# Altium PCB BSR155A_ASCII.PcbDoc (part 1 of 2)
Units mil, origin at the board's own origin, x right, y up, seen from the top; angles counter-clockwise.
Board outline 3250 x 2500 mil, 4 copper layers (Top Layer, MidLayer1, MidLayer2, Bottom Layer), stack 59.8 mil thick; 70 components, 25 nets, 149 pads, 70 vias.
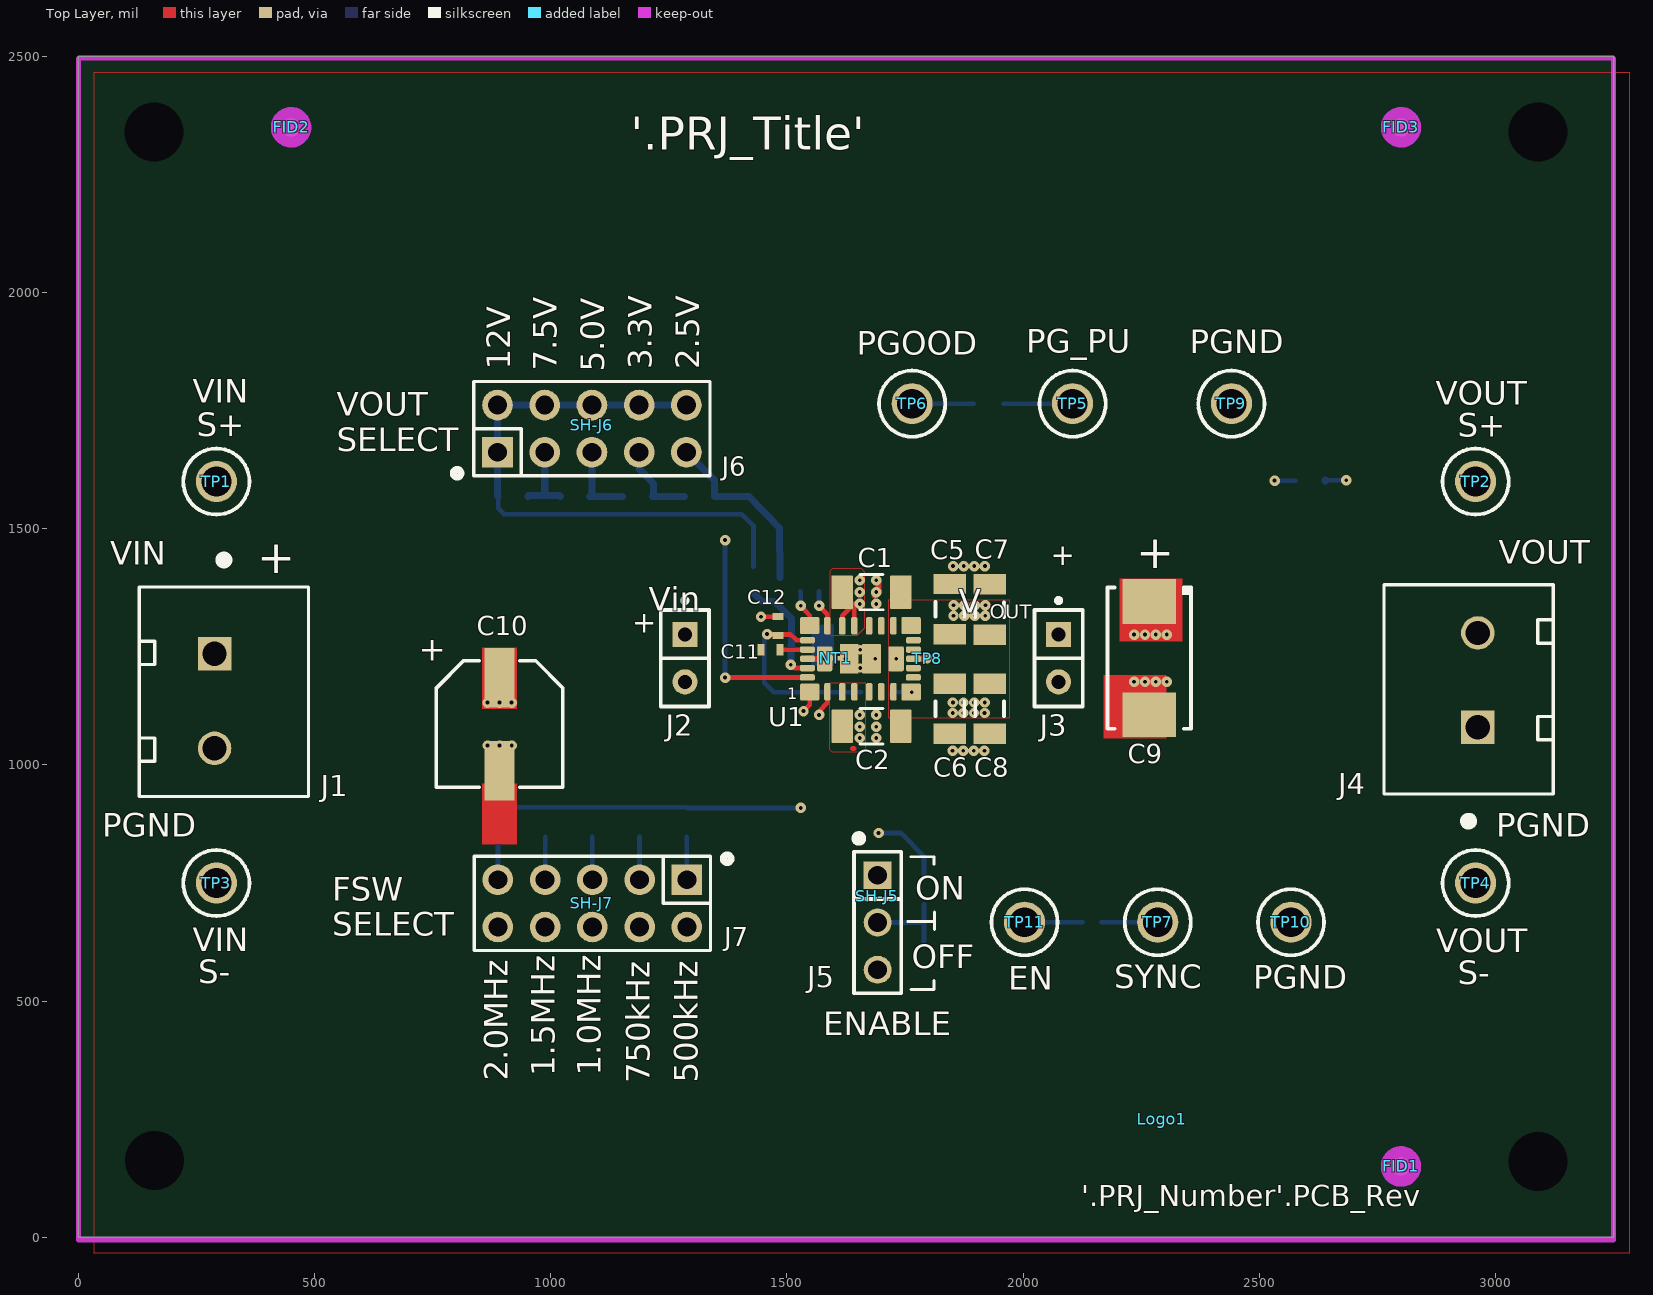
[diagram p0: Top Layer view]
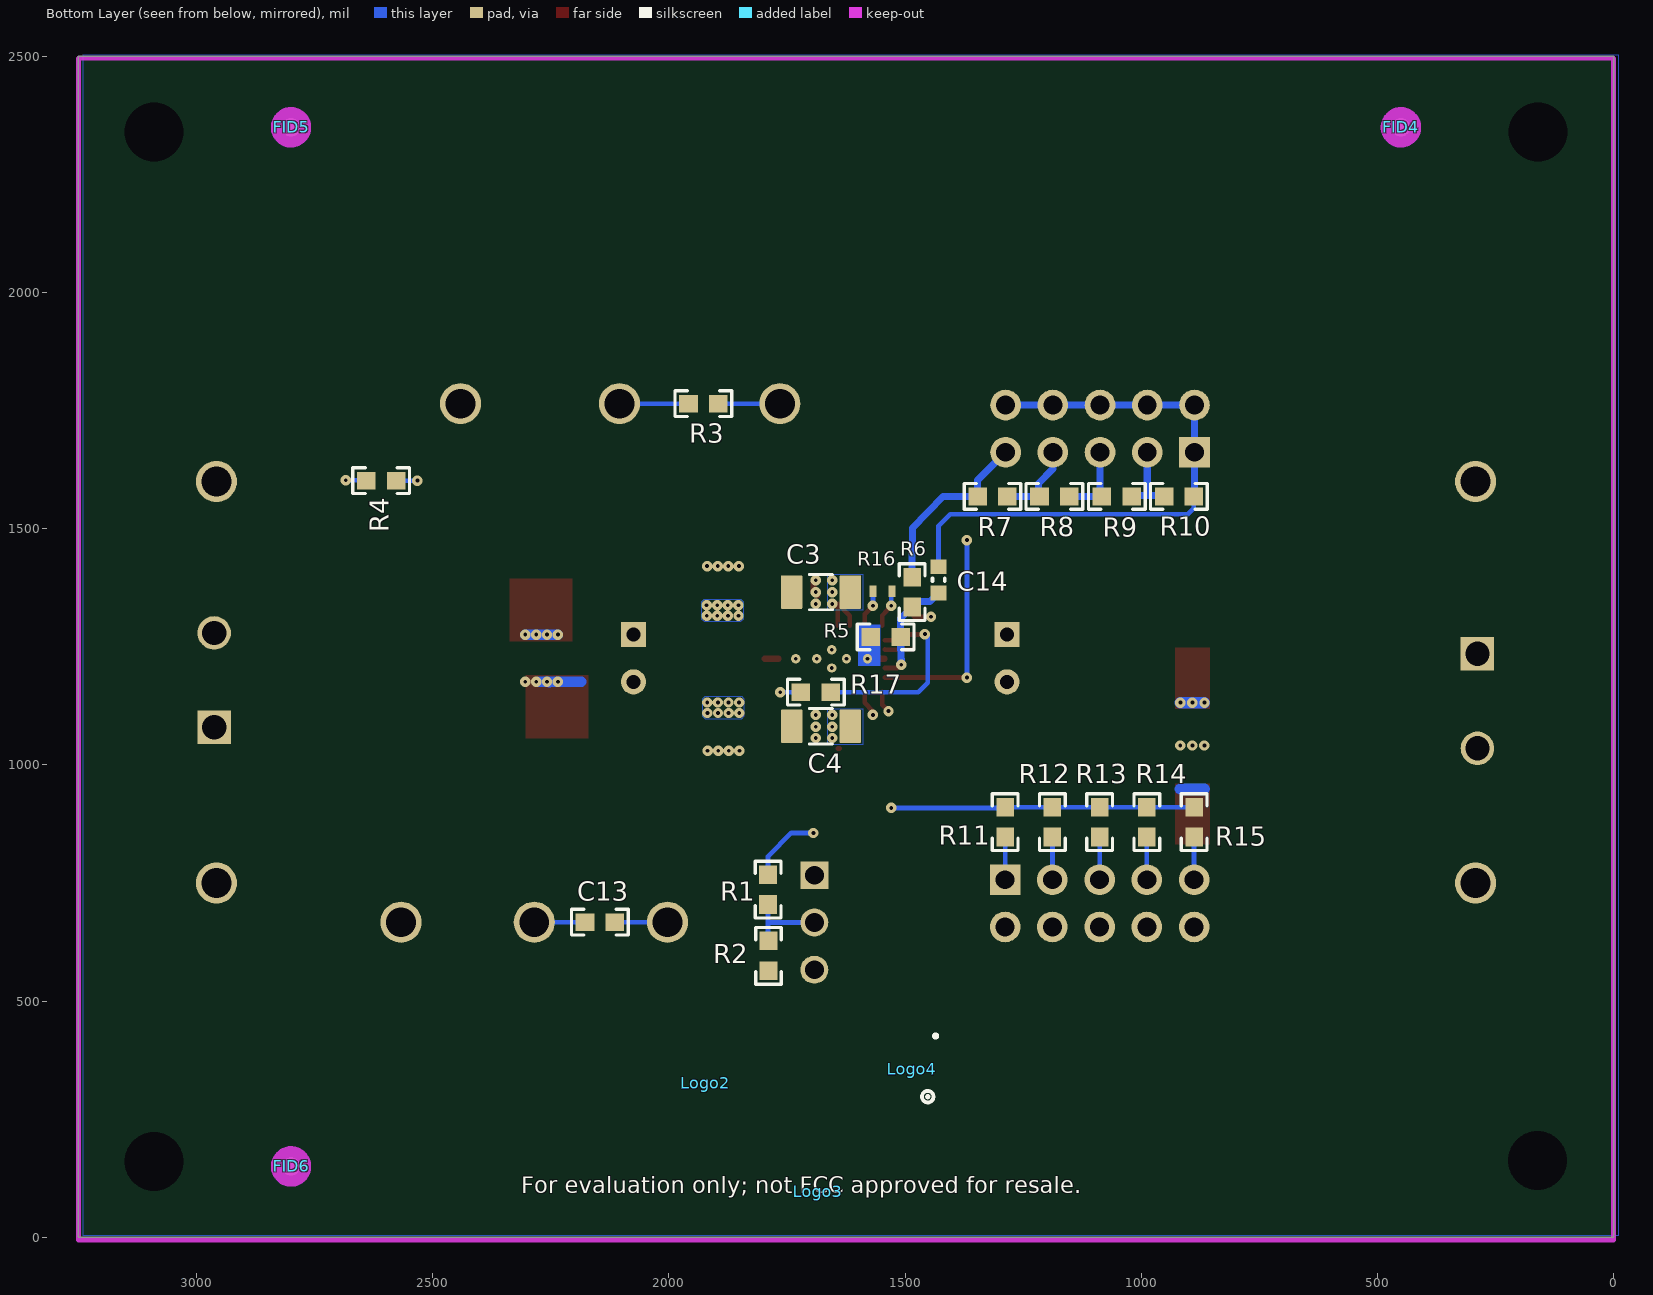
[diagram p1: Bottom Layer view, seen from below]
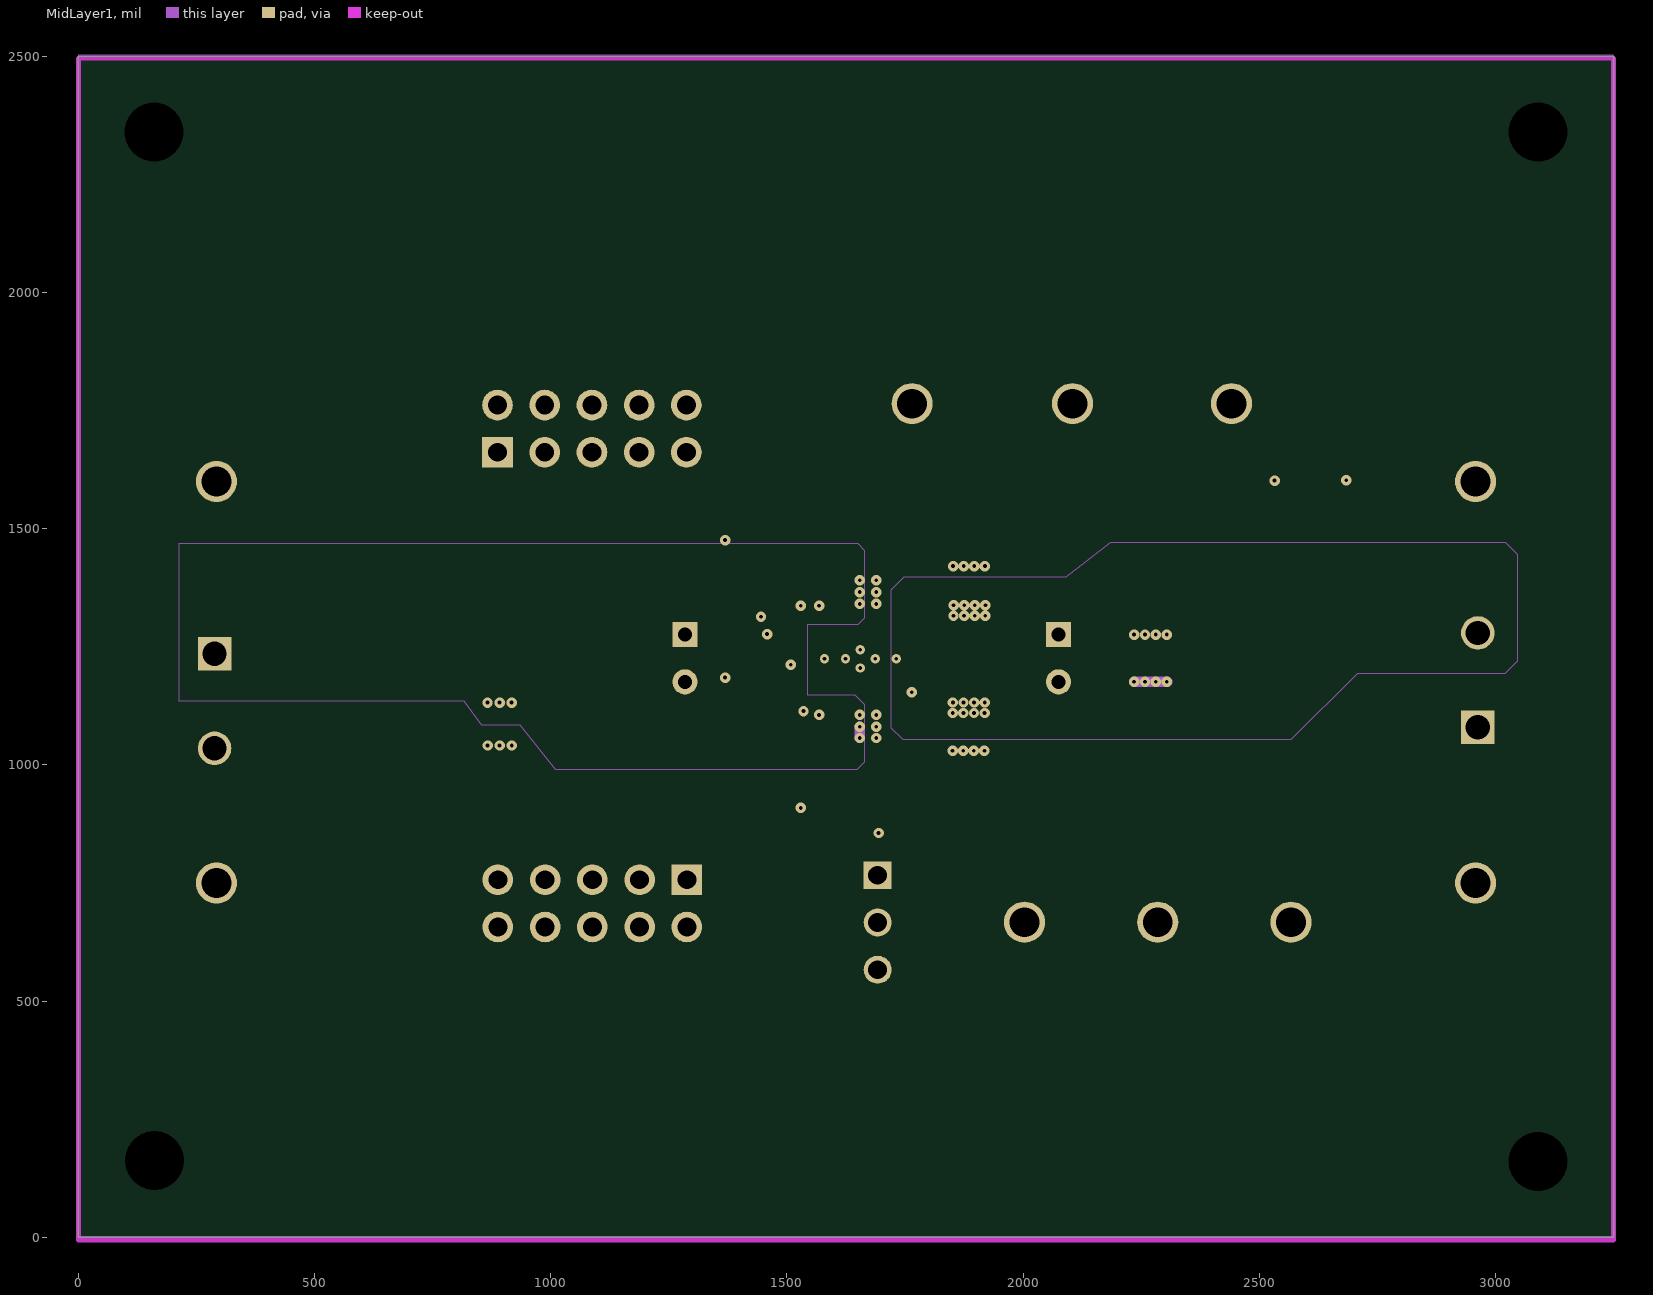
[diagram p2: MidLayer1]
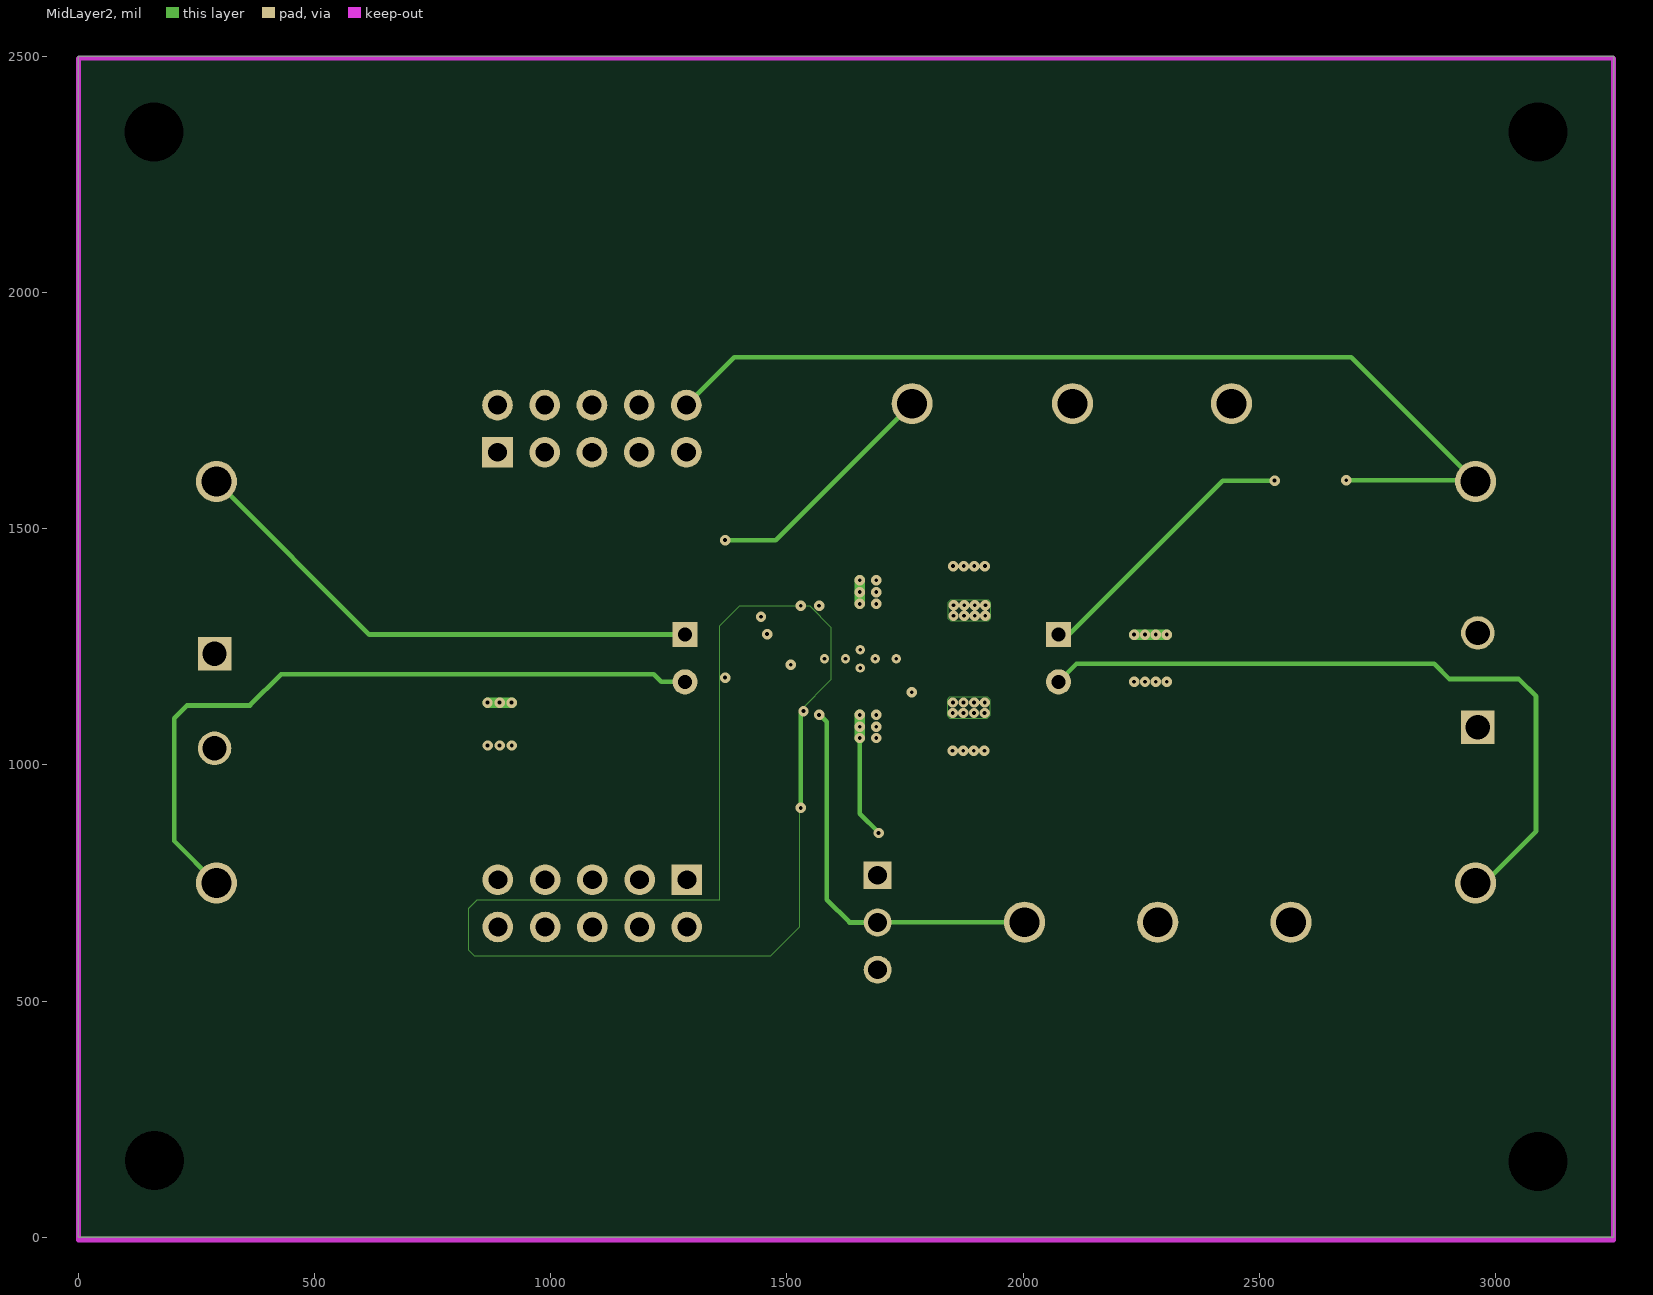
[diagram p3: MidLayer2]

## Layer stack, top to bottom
Top Solder: solder mask 0.4, Solder Resist, Dk 3.5
Top Layer: signal copper 1.4
Dielectric1: prepreg 5, FR-4 High Tg, Dk 4.2
MidLayer1: signal copper 2.8
Dielectric2: core 40, FR-4 High Tg, Dk 4.2
MidLayer2: signal copper 2.8
Dielectric3: prepreg 5, FR-4 High Tg, Dk 4.2
Bottom Layer: signal copper 2.8
Bottom Solder: solder mask 0.4, Solder Resist, Dk 3.5

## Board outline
0,0 0,2500 3250,2500 3250,0

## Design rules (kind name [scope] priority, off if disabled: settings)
AcuteAngle [All] p0: scope1count=1 scope1_0_kind=Board scope1_0_value=Board scope2count=1 scope2_0_kind=Board scope2_0_value=Board commentlength=0 minimum=4.50000000000000E+0001
AcuteAngle [All] p1: minimum=4.50000000000000E+0001 checktracksonly=TRUE
AssemblyTestPointUsage [All] p0: scope1count=1 scope1_0_kind=Board scope1_0_value=Board scope2count=1 scope2_0_kind=Board scope2_0_value=Board commentlength=0
AssemblyTestPointUsage [All] p1: valid=2
AssemblyTestpoint [All] p0: scope1count=1 scope1_0_kind=Board scope1_0_value=Board scope2count=1 scope2_0_kind=Board scope2_0_value=Board commentlength=0
BoardOutlineClearance [All] p0 off: scope1count=1 scope1_0_kind=Board scope1_0_value=Board scope2count=1 scope2_0_kind=Board scope2_0_value=Board commentlength=172 gap=20 // Protel DXP Scope 1 Expression Was: OnCopper and Not InComponentClass('Logo') and not InComponentClass('FiducialMark') and not InRegion(1000,500,4000,800) and not InPoly
BoardOutlineClearance BoardOutlineClearance_Poly [All] p0 off: scope1count=1 scope1_0_kind=Board scope1_0_value=Board scope2count=1 scope2_0_kind=Board scope2_0_value=Board commentlength=58 gap=20 // Protel DXP Scope 1 Expression Was: OnCopper and IsPoly
BoardOutlineClearance BoardOutlineClearance_MountingHoles [All] p0 off: scope1count=1 scope1_0_kind=Board scope1_0_value=Board scope2count=1 scope2_0_kind=Board scope2_0_value=Board commentlength=86 gap=40 // Protel DXP Scope 1 Expression Was: OnCopper and InComponentClass('Mounting Holes')
BoardOutlineClearance BoardOutlineClearance_MountingHoles [OnCopper and InComponentClass('Mounting Holes')] p1: gap=40 ignorepadtopadclearanceinfootprint=FALSE
BoardOutlineClearance BoardOutlineClearance_Poly [OnCopper and IsPoly] p2: gap=20 ignorepadtopadclearanceinfootprint=FALSE
BoardOutlineClearance [OnCopper and Not InComponentClass('Logo') and not InComponentClass('FiducialMark') and not InRegion(1000,500,4000,800) and not InPoly] p3: gap=20 ignorepadtopadclearanceinfootprint=FALSE
Clearance [All] p0: scope1count=1 scope1_0_kind=Board scope1_0_value=Board scope2count=1 scope2_0_kind=Board scope2_0_value=Board commentlength=0 gap=10
Clearance Clearance_FiducialMark [All] p0 off: scope1count=1 scope1_0_kind=Board scope1_0_value=Board scope2count=1 scope2_0_kind=Board scope2_0_value=Board commentlength=81 gap=0 // Protel DXP Scope 2 Expression Was: IsPad and InComponentClass('FiducialMark')
Clearance Clearance_Poly [All] p0 off: scope1count=1 scope1_0_kind=Board scope1_0_value=Board scope2count=1 scope2_0_kind=Board scope2_0_value=Board commentlength=48 gap=10 // Protel DXP Scope 1 Expression Was: InPolygon
Clearance Clearance_Keepouts [All] p0 off: scope1count=1 scope1_0_kind=Board scope1_0_value=Board scope2count=1 scope2_0_kind=Board scope2_0_value=Board commentlength=99 gap=0 // Protel DXP Scope 2 Expression Was: ((IsTrack Or IsArc) And Not InPoly) And IsFree and IsKeepOut
Clearance Clearance_Keepouts [((IsTrack Or IsArc) And Not InPoly) And IsFree and IsKeepOut vs ((IsTrack Or IsArc) And Not InPoly) And IsFree and IsKeepOut] p1: gap=0 ignorepadtopadclearanceinfootprint=FALSE
Clearance Clearance_Poly [InPolygon] p2: gap=10 ignorepadtopadclearanceinfootprint=FALSE except(0: Arc-Hole Track-Hole SMDPad-Hole THPad-Hole Via-Hole Fill-Hole Poly-Hole Region-Hole Text-Hole)
Clearance Clearance_FiducialMark [IsKeepOut and InComponentClass('FiducialMark') vs IsPad and InComponentClass('FiducialMark')] p3: gap=0 ignorepadtopadclearanceinfootprint=FALSE
Clearance [All] p4: gap=10 ignorepadtopadclearanceinfootprint=FALSE except(0: Arc-Hole Track-Hole SMDPad-Hole THPad-Hole Via-Hole Fill-Hole Poly-Hole Region-Hole Text-Hole; 4: SMDPad-SMDPad; 6: Arc-SMDPad Track-SMDPad SMDPad-THPad; 8: Arc-Arc Arc-Track Track-Track)
ComponentClearance "ComponentClearance_U1 to NT1" [All] p0: scope1count=1 scope1_0_kind=Component scope1_0_value=NT1 scope2count=1 scope2_0_kind=Component scope2_0_value=U1 commentlength=0 gap=0 collisioncheckmode=3
ComponentClearance [All] p0: scope1count=1 scope1_0_kind=Board scope1_0_value=Board scope2count=1 scope2_0_kind=Board scope2_0_value=Board commentlength=0 gap=10 collisioncheckmode=3
ComponentClearance ComponentClearance_THtoTH [All] p0 off: scope1count=1 scope1_0_kind=Board scope1_0_value=Board scope2count=1 scope2_0_kind=Board scope2_0_value=Board commentlength=54 gap=10 collisioncheckmode=3 // Protel DXP Scope 2 Expression Was: IsThruComponent
ComponentClearance ComponentClearance_THtoSMT [All] p0 off: scope1count=1 scope1_0_kind=Board scope1_0_value=Board scope2count=1 scope2_0_kind=Board scope2_0_value=Board commentlength=53 gap=10 collisioncheckmode=3 // Protel DXP Scope 2 Expression Was: IsSMTComponent
ComponentClearance ComponentClearance_SmallPassives [All] p0 off: scope1count=1 scope1_0_kind=Board scope1_0_value=Board scope2count=1 scope2_0_kind=Board scope2_0_value=Board commentlength=508 gap=8 collisioncheckmode=3 // Protel DXP Scope 2 Expression Was: HasFootprint('0201*') or HasFootprint('0402*') or HasFootprint('0508') or HasFootprint('0603*') or HasFootprint('0612') or HasFootprint('0805*') or HasFootprint('0815*') or HasFootprint('0830*') or HasFootprint('1206*') or HasFootprint('1210*') or HasFootprint('1808*') or HasFootprint('1812*') or HasFootprint('1825*') or HasFootprint('2010*') or HasFootprint('2220*') or HasFootprint('2225*') or HasFootprint('2512*') or HasFootprint('2728*') or HasFootprint('3518*')
ComponentClearance ComponentClearance_MountingHoles [All] p0: scope1count=1 scope1_0_kind=ComponentClass scope1_0_value="Mounting Holes" scope2count=1 scope2_0_kind=Board scope2_0_value=Board commentlength=0 gap=10 collisioncheckmode=3
ComponentClearance ComponentClearance_ScrewToNut [All] p0 off: scope1count=1 scope1_0_kind=Board scope1_0_value=Board scope2count=1 scope2_0_kind=Board scope2_0_value=Board commentlength=71 gap=5 collisioncheckmode=3 // Protel DXP Scope 2 Expression Was: (HasFootprint('Keystone_1902C'))
ComponentClearance ComponentClearance_Logo [All] p0: scope1count=1 scope1_0_kind=ComponentClass scope1_0_value=Logo scope2count=1 scope2_0_kind=Board scope2_0_value=Board commentlength=0 gap=10 collisioncheckmode=3
ComponentClearance ComponentClearance_Shunt [All] p0: scope1count=1 scope1_0_kind=ComponentClass scope1_0_value=Header scope2count=1 scope2_0_kind=ComponentClass scope2_0_value=Shunt commentlength=0 gap=0 collisioncheckmode=3
ComponentClearance ComponentClearance_MountingHoles_FiducialMarks [All] p0: scope1count=1 scope1_0_kind=ComponentClass scope1_0_value="Mounting Holes" scope2count=1 scope2_0_kind=ComponentClass scope2_0_value=FiducialMark commentlength=0 gap=10 collisioncheckmode=3
ComponentClearance ComponentClearance_MountingHoles_FiducialMarks [InComponentClass('Mounting Holes') vs InComponentClass('FiducialMark')] p1: gap=10 collisioncheckmode=3 verticalgap=10 showdistances=FALSE
ComponentClearance ComponentClearance_Shunt [InComponentClass('Header') vs InComponentClass('Shunt')] p2: gap=0 collisioncheckmode=3 verticalgap=0 showdistances=FALSE
ComponentClearance ComponentClearance_Logo [InComponentClass('Logo')] p3: gap=10 collisioncheckmode=3 verticalgap=10 showdistances=FALSE
ComponentClearance ComponentClearance_ScrewToNut [(HasFootprint('NY PMS 440 0025 PH')) vs (HasFootprint('Keystone_1902C'))] p4: gap=5 collisioncheckmode=3 verticalgap=10 showdistances=FALSE
ComponentClearance ComponentClearance_MountingHoles [InComponentClass('Mounting Holes')] p5: gap=10 collisioncheckmode=3 verticalgap=100000 showdistances=FALSE
ComponentClearance ComponentClearance_SmallPassives [HasFootprint('0201*') or HasFootprint('0402*') or HasFootprint('0508') or HasFootprint('0603*') or HasFootprint('0612') or HasFootprint('0805*') or HasFootprint('0815*') or HasFootprint('0830*') or HasFootprint('1206*') or HasFootprint('1210*') or HasFootprint('1808*') or HasFootprint('1812*') or HasFootprint('1825*') or HasFootprint('2010*') or HasFootprint('2220*') or HasFootprint('2225*') or HasFootprint('2512*') or HasFootprint('2728*') or HasFootprint('3518*') vs HasFootprint('0201*') or HasFootprint('0402*') or HasFootprint('0508') or HasFootprint('0603*') or HasFootprint('0612') or HasFootprint('0805*') or HasFootprint('0815*') or HasFootprint('0830*') or HasFootprint('1206*') or HasFootprint('1210*') or HasFootprint('1808*') or HasFootprint('1812*') or HasFootprint('1825*') or HasFootprint('2010*') or HasFootprint('2220*') or HasFootprint('2225*') or HasFootprint('2512*') or HasFootprint('2728*') or HasFootprint('3518*')] p6: gap=8 collisioncheckmode=3 verticalgap=8 showdistances=FALSE
ComponentClearance ComponentClearance_THtoSMT [IsThruComponent vs IsSMTComponent] p7: gap=10 collisioncheckmode=3 verticalgap=30 showdistances=FALSE
ComponentClearance ComponentClearance_THtoTH [IsThruComponent vs IsThruComponent] p8: gap=10 collisioncheckmode=3 verticalgap=30 showdistances=FALSE
ComponentClearance "ComponentClearance_U1 to NT1" [InComponent('NT1') vs InComponent('U1')] p9: gap=0 collisioncheckmode=3 verticalgap=0 showdistances=FALSE
ComponentClearance [All] p10: gap=10 collisioncheckmode=3 verticalgap=30 showdistances=FALSE
DiffPairsRouting [All] p0: scope1count=1 scope1_0_kind=Board scope1_0_value=Board scope2count=1 scope2_0_kind=Board scope2_0_value=Board commentlength=0
DiffPairsRouting [All] p1: maxlimit=100 minlimit=10 mostfreqgap=10 toplayer_minwidth=15 toplayer_maxwidth=15 toplayer_prefwidth=15 midlayer1_minwidth=15 midlayer1_maxwidth=15 midlayer1_prefwidth=15 midlayer2_minwidth=15 midlayer2_maxwidth=15 midlayer2_prefwidth=15 bottomlayer_minwidth=15 bottomlayer_maxwidth=15 bottomlayer_prefwidth=15 maxuncoupledlength=1000
FabricationTestPointUsage TestPointUsage [All] p0: scope1count=1 scope1_0_kind=Board scope1_0_value=Board scope2count=1 scope2_0_kind=Board scope2_0_value=Board commentlength=0 valid=2 allowmultiple=FALSE
FabricationTestPointUsage TestPointUsage [All] p1: valid=2 allowmultiple=FALSE
FabricationTestpoint Testpoint [All] p0: scope1count=1 scope1_0_kind=Board scope1_0_value=Board scope2count=1 scope2_0_kind=Board scope2_0_value=Board commentlength=0 side=3 testpointundercomponent=TRUE minsize=40 maxsize=100 preferedsize=60 minholesize=0 maxholesize=40 preferedholesize=32 testpointgrid=1
FabricationTestpoint Testpoint [All] p1: side=3 testpointundercomponent=TRUE minsize=40 maxsize=100 preferedsize=60 minholesize=0 maxholesize=40 preferedholesize=32 testpointgrid=1 allowsidetop=TRUE allowsidebottom=TRUE usegrid=TRUE gridtolerance=0.01
FanoutControl Fanout_Small [All] p0 off: scope1count=1 scope1_0_kind=Board scope1_0_value=Board scope2count=1 scope2_0_kind=Board scope2_0_value=Board commentlength=84 // Protel DXP Scope 1 Expression Was: (CompPinCount < 5)   Fanout_Small (Default Rule)
FanoutControl Fanout_Default [All] p0: scope1count=1 scope1_0_kind=Board scope1_0_value=Board scope2count=1 scope2_0_kind=Board scope2_0_value=Board commentlength=30 // Fanout_Default (Default Rule)
FanoutControl Fanout_SOIC [All] p0 off: scope1count=1 scope1_0_kind=Board scope1_0_value=Board scope2count=1 scope2_0_kind=Board scope2_0_value=Board commentlength=71 // Protel DXP Scope 1 Expression Was: IsSOIC   Fanout_SOIC (Default Rule)
FanoutControl Fanout_BGA [All] p0 off: scope1count=1 scope1_0_kind=Board scope1_0_value=Board scope2count=1 scope2_0_kind=Board scope2_0_value=Board commentlength=69 // Protel DXP Scope 1 Expression Was: IsBGA   Fanout_BGA (Default Rule)
FanoutControl Fanout_LCC [All] p0 off: scope1count=1 scope1_0_kind=Board scope1_0_value=Board scope2count=1 scope2_0_kind=Board scope2_0_value=Board commentlength=69 // Protel DXP Scope 1 Expression Was: IsLCC   Fanout_LCC (Default Rule)
FanoutControl Fanout_LCC [IsLCC] p1: bgadir=Out bgaviamode=Centered fanoutstyle=Auto fanoutdirection=Alternating viagrid=1 // Fanout_LCC (Default Rule)
FanoutControl Fanout_BGA [IsBGA] p2: bgadir=Out bgaviamode=Centered fanoutstyle=Auto fanoutdirection=Alternating viagrid=1 // Fanout_BGA (Default Rule)
FanoutControl Fanout_Default [All] p4: bgadir=Out bgaviamode=Centered fanoutstyle=Auto fanoutdirection=Alternating viagrid=1 // Fanout_Default (Default Rule)
FanoutControl Fanout_Small [(CompPinCount < 5)] p5: bgadir=Out bgaviamode=Centered fanoutstyle=Auto fanoutdirection=OutThenIn viagrid=1 // Fanout_Small (Default Rule)
Height [All] p0: scope1count=1 scope1_0_kind=Board scope1_0_value=Board scope2count=1 scope2_0_kind=Board scope2_0_value=Board commentlength=0
Height [All] p1: minheight=0 maxheight=10000 prefheight=500
HoleSize [All] p0: scope1count=1 scope1_0_kind=Board scope1_0_value=Board scope2count=1 scope2_0_kind=Board scope2_0_value=Board commentlength=0 absolutevalues=TRUE maxlimit=251 minlimit=6 maxpercent=80.000 minpercent=20.000
HoleSize [All] p1: absolutevalues=TRUE maxlimit=251 minlimit=6 maxpercent=80.000 minpercent=20.000
HoleToHoleClearance [All] p0: scope1count=1 scope1_0_kind=Board scope1_0_value=Board scope2count=1 scope2_0_kind=Board scope2_0_value=Board commentlength=0
LayerPairs [All] p0: scope1count=1 scope1_0_kind=Board scope1_0_value=Board scope2count=1 scope2_0_kind=Board scope2_0_value=Board commentlength=0 enforce=TRUE
MinimumAnnularRing [All] p0: scope1count=1 scope1_0_kind=Board scope1_0_value=Board scope2count=1 scope2_0_kind=Board scope2_0_value=Board commentlength=0 minimumring=5
MinimumAnnularRing MinimumAnnularRing_ThermalPadVias [All] p0 off: scope1count=1 scope1_0_kind=Board scope1_0_value=Board scope2count=1 scope2_0_kind=Board scope2_0_value=Board commentlength=63 minimumring=5 // Protel DXP Scope 1 Expression Was: IsVia and InAnyComponent
MinimumAnnularRing MinimumAnnularRing_ThermalPadVias [IsVia and InAnyComponent] p1: minimumring=5
MinimumAnnularRing [All] p2: minimumring=5
MinimumSolderMaskSliver [All] p0: scope1count=1 scope1_0_kind=Board scope1_0_value=Board scope2count=1 scope2_0_kind=Board scope2_0_value=Board commentlength=0
MinimumSolderMaskSliver MinimumSolderMaskSliver_Logo [All] p0: scope1count=1 scope1_0_kind=ComponentClass scope1_0_value=Logo scope2count=1 scope2_0_kind=ComponentClass scope2_0_value=Logo commentlength=0
MinimumSolderMaskSliver MinimumSolderMaskSliver_1 [All] p0 off: scope1count=1 scope1_0_kind=Footprint scope1_0_value=RDA0015A-MFG scope2count=1 scope2_0_kind=Board scope2_0_value=Board commentlength=68 // Protel DXP Scope 2 Expression Was: (InComponent('U1') AND IsVia)
MinimumSolderMaskSliver MinimumSolderMaskSliver_1 [HasFootprint('RDA0015A-MFG') vs (InComponent('U1') AND IsVia)] p1: minsoldermaskwidth=1
MinimumSolderMaskSliver MinimumSolderMaskSliver_Logo [InComponentClass('Logo') vs InComponentClass('Logo')] p2: minsoldermaskwidth=0.7
MinimumSolderMaskSliver [All] p3: minsoldermaskwidth=3.94
NetAntennae [All] p0: scope1count=1 scope1_0_kind=Board scope1_0_value=Board scope2count=1 scope2_0_kind=Board scope2_0_value=Board commentlength=0
PasteMaskExpansion [All] p0: scope1count=1 scope1_0_kind=Board scope1_0_value=Board scope2count=1 scope2_0_kind=Board scope2_0_value=Board commentlength=0 expansion=0
PlaneClearance [All] p0: scope1count=1 scope1_0_kind=Board scope1_0_value=Board scope2count=1 scope2_0_kind=Board scope2_0_value=Board commentlength=0 clearance=9.84
PlaneClearance PlaneClearance_1 [All] p0: scope1count=1 scope1_0_kind=Layer scope1_0_value=TOP scope2count=1 scope2_0_kind=Board scope2_0_value=Board commentlength=0 clearance=7.87
PlaneClearance PlaneClearance_1 [OnLayer('Top Layer')] p1: clearance=7.87
PlaneClearance [All] p2: clearance=9.84
PlaneConnect [All] p0: scope1count=1 scope1_0_kind=Board scope1_0_value=Board scope2count=1 scope2_0_kind=Board scope2_0_value=Board commentlength=0 planeconnectstyle=Relief reliefexpansion=10 reliefentries=4 reliefconductorwidth=10 reliefairgap=10
PlaneConnect PlaneConnect_via [All] p0 off: scope1count=1 scope1_0_kind=Board scope1_0_value=Board scope2count=1 scope2_0_kind=Board scope2_0_value=Board commentlength=44 planeconnectstyle=Direct reliefexpansion=20 reliefentries=4 reliefconductorwidth=10 reliefairgap=10 // Protel DXP Scope 1 Expression Was: IsVia
PlaneConnect PlaneConnect_via [IsVia] p1: planeconnectstyle=Direct reliefexpansion=20 reliefentries=4 reliefconductorwidth=10 reliefairgap=10
PlaneConnect [All] p2: planeconnectstyle=Relief reliefexpansion=10 reliefentries=4 reliefconductorwidth=10 reliefairgap=10
PolygonConnect [All] p0: scope1count=1 scope1_0_kind=Board scope1_0_value=Board scope2count=1 scope2_0_kind=Board scope2_0_value=Board commentlength=0 connectstyle=Relief reliefconductorwidth=10 reliefentries=4 polygonreliefangle="90 Angle"
PolygonConnect PolygonConnect_poly [All] p0 off: scope1count=1 scope1_0_kind=Board scope1_0_value=Board scope2count=1 scope2_0_kind=Board scope2_0_value=Board commentlength=45 connectstyle=Direct reliefconductorwidth=10 reliefentries=4 polygonreliefangle="90 Angle" // Protel DXP Scope 1 Expression Was: IsPoly
PolygonConnect PolygonConnect_1 [All] p0 off: scope1count=1 scope1_0_kind=Board scope1_0_value=Board scope2count=1 scope2_0_kind=Board scope2_0_value=Board commentlength=97 connectstyle=Relief reliefconductorwidth=20 reliefentries=4 polygonreliefangle="90 Angle" // Protel DXP Scope 1 Expression Was: IsThruPin AND NOT (InComponent('J3') or InComponent('J2'))
PolygonConnect PolygonConnect_Via [All] p0 off: scope1count=1 scope1_0_kind=Board scope1_0_value=Board scope2count=1 scope2_0_kind=Board scope2_0_value=Board commentlength=44 connectstyle=Direct reliefconductorwidth=10 reliefentries=4 polygonreliefangle="90 Angle" // Protel DXP Scope 1 Expression Was: IsVia
PolygonConnect PolygonConnect_logo [All] p0: scope1count=1 scope1_0_kind=Component scope1_0_value=Logo1 scope2count=1 scope2_0_kind=Board scope2_0_value=Board commentlength=0 connectstyle=Direct reliefconductorwidth=10 reliefentries=4 polygonreliefangle="90 Angle"
PolygonConnect PolygonConnect_tp [All] p0 off: scope1count=1 scope1_0_kind=Board scope1_0_value=Board scope2count=1 scope2_0_kind=Board scope2_0_value=Board commentlength=111 connectstyle=NoConnect reliefconductorwidth=25 reliefentries=4 polygonreliefangle="90 Angle" // Protel DXP Scope 1 Expression Was: (InComponent('TP*') and not (InComponent('TP9') or InComponent('TP10')))
PolygonConnect PolygonConnect_ESD120 [All] p0: scope1count=1 scope1_0_kind=Footprint scope1_0_value=On-Shore_ED120_2DS scope2count=1 scope2_0_kind=Board scope2_0_value=Board commentlength=0 connectstyle=Relief reliefconductorwidth=25 reliefentries=4 polygonreliefangle="90 Angle"
PolygonConnect PolygonConnect_ESD120 [HasFootprint('On-Shore_ED120_2DS')] p1: connectstyle=Relief reliefconductorwidth=25 reliefentries=4 polygonreliefangle="90 Angle" airgapwidth=10
PolygonConnect PolygonConnect_tp [(InComponent('TP*') and not (InComponent('TP9') or InComponent('TP10')))] p2: connectstyle=NoConnect reliefconductorwidth=25 reliefentries=4 polygonreliefangle="90 Angle" airgapwidth=10
PolygonConnect PolygonConnect_logo [InComponent('Logo1')] p3: connectstyle=Direct reliefconductorwidth=10 reliefentries=4 polygonreliefangle="90 Angle" airgapwidth=10
PolygonConnect PolygonConnect_Via [IsVia] p4: connectstyle=Direct reliefconductorwidth=10 reliefentries=4 polygonreliefangle="90 Angle" airgapwidth=10
PolygonConnect PolygonConnect_1 [IsThruPin AND NOT (InComponent('J3') or InComponent('J2'))] p5: connectstyle=Relief reliefconductorwidth=20 reliefentries=4 polygonreliefangle="90 Angle" airgapwidth=10
PolygonConnect PolygonConnect_poly [IsPoly] p6: connectstyle=Direct reliefconductorwidth=10 reliefentries=4 polygonreliefangle="90 Angle" airgapwidth=8
PolygonConnect [All] p7: connectstyle=Relief reliefconductorwidth=10 reliefentries=4 polygonreliefangle="90 Angle" airgapwidth=8
RoutingCorners [All] p0: scope1count=1 scope1_0_kind=Board scope1_0_value=Board scope2count=1 scope2_0_kind=Board scope2_0_value=Board commentlength=0 cornerstyle=45-Degree minsetback=100 maxsetback=100
RoutingLayers [All] p0: scope1count=1 scope1_0_kind=Board scope1_0_value=Board scope2count=1 scope2_0_kind=Board scope2_0_value=Board commentlength=0 top layer=Automatic mid layer 1=Automatic mid layer 2=Automatic bottom layer=Automatic
RoutingPriority [All] p0: scope1count=1 scope1_0_kind=Board scope1_0_value=Board scope2count=1 scope2_0_kind=Board scope2_0_value=Board commentlength=0
RoutingTopology [All] p0: scope1count=1 scope1_0_kind=Board scope1_0_value=Board scope2count=1 scope2_0_kind=Board scope2_0_value=Board commentlength=0 topology=Shortest
RoutingVias [All] p0: scope1count=1 scope1_0_kind=Board scope1_0_value=Board scope2count=1 scope2_0_kind=Board scope2_0_value=Board commentlength=0 holewidth=16 width=34 viastyle="Through Hole" minholewidth=6 minwidth=19 maxholewidth=40 maxwidth=65
RoutingVias ThermalPadVias [All] p0 off: scope1count=1 scope1_0_kind=Board scope1_0_value=Board scope2count=1 scope2_0_kind=Board scope2_0_value=Board commentlength=63 holewidth=7.87 width=19.68 viastyle="Through Hole" minholewidth=7.87 minwidth=19.68 maxholewidth=12.99 maxwidth=23.62 // Protel DXP Scope 1 Expression Was: IsVia and InAnyComponent
RoutingVias ThermalPadVias [IsVia and InAnyComponent] p1: holewidth=7.87 width=19.68 viastyle="Through Hole" minholewidth=7.87 minwidth=19.68 maxholewidth=12.99 maxwidth=23.62
RoutingVias [All] p2: holewidth=16 width=34 viastyle="Through Hole" minholewidth=6 minwidth=19 maxholewidth=40 maxwidth=65
ShortCircuit [All] p0: scope1count=1 scope1_0_kind=Board scope1_0_value=Board scope2count=1 scope2_0_kind=Board scope2_0_value=Board commentlength=0 allowed=FALSE
SilkToBoardRegionClearance SilkToBoardRegionClearance_1 [All] p0: scope1count=1 scope1_0_kind=Board scope1_0_value=Board scope2count=1 scope2_0_kind=Board scope2_0_value=Board commentlength=0
SilkToBoardRegionClearance SilkToBoardRegionClearance_1 [All] p1:
SilkToSilkClearance [All] p0: scope1count=1 scope1_0_kind=Board scope1_0_value=Board scope2count=1 scope2_0_kind=Board scope2_0_value=Board commentlength=0
SilkToSilkClearance SilkToSilkClearance_Pb-FreeLogo [All] p0 off: scope1count=1 scope1_0_kind=Board scope1_0_value=Board scope2count=1 scope2_0_kind=Board scope2_0_value=Board commentlength=120 // Protel DXP Scope 2 Expression Was: (HasFootprint('Pb-Free_Overlay_Medium') OR HasFootprint('Pb-Free_Overlay_Small'))
SilkToSilkClearance SilkToSilkClearance_Pb-FreeLogo [(HasFootprint('Pb-Free_Overlay_Medium') OR HasFootprint('Pb-Free_Overlay_Small')) vs (HasFootprint('Pb-Free_Overlay_Medium') OR HasFootprint('Pb-Free_Overlay_Small'))] p1: silktosilkclearance=0
SilkToSilkClearance [All] p2: silktosilkclearance=3
SilkToSolderMaskClearance "Silk to Solder Mask Opening" [All] p0: scope1count=1 scope1_0_kind=Board scope1_0_value=Board scope2count=1 scope2_0_kind=Board scope2_0_value=Board commentlength=0
SilkToSolderMaskClearance SilkToComponentPadClearance [All] p0 off: scope1count=1 scope1_0_kind=Board scope1_0_value=Board scope2count=1 scope2_0_kind=Board scope2_0_value=Board commentlength=87 // Protel DXP Scope 1 Expression Was: (IsPad or IsFill or IsRegion) and InAnycomponent
SilkToSolderMaskClearance "Cap silkscreen on vias" [All] p0 off: scope1count=1 scope1_0_kind=Board scope1_0_value=Board scope2count=1 scope2_0_kind=Board scope2_0_value=Board commentlength=44 // Protel DXP Scope 2 Expression Was: IsVia
SilkToSolderMaskClearance "Cap silkscreen on vias" [IsTrack and (InComponent('C1') or InComponent('C11') or InComponent('C12') or InComponent('C2')or InComponent('C5') or InComponent('C6') or InComponent('C7') or InComponent('C8') or InComponent('C13') or InComponent('C14') or InComponent('C15') or InComponent('C16') or InComponent('C11') or InComponent('C12') or InComponent('C3') or InComponent('C4') or InComponent('R1') or InComponent('R2') or InComponent('U1')) vs IsVia] p1: minsilkscreentomaskgap=0 clearancetoexposedcopper=FALSE
SilkToSolderMaskClearance SilkToComponentPadClearance [(IsPad or IsFill or IsRegion) and InAnycomponent] p2: minsilkscreentomaskgap=4.8 clearancetoexposedcopper=TRUE
SilkToSolderMaskClearance "Silk to Solder Mask Opening" [All] p3: minsilkscreentomaskgap=4 clearancetoexposedcopper=FALSE
SolderMaskExpansion [All] p0: scope1count=1 scope1_0_kind=Board scope1_0_value=Board scope2count=1 scope2_0_kind=Board scope2_0_value=Board commentlength=0 expansion=1.97
SolderMaskExpansion [All] p1: expansion=1.97
UnRoutedNet [All] p0: scope1count=1 scope1_0_kind=Board scope1_0_value=Board scope2count=1 scope2_0_kind=Board scope2_0_value=Board commentlength=0
UnpouredPolygon [All] p0: scope1count=1 scope1_0_kind=Board scope1_0_value=Board scope2count=1 scope2_0_kind=Board scope2_0_value=Board commentlength=0
Width [All] p0: scope1count=1 scope1_0_kind=Board scope1_0_value=Board scope2count=1 scope2_0_kind=Board scope2_0_value=Board commentlength=0 maxlimit=100 minlimit=6 preferedwidth=10
Width [All] p1: maxlimit=100 minlimit=6 preferedwidth=10 checkconnectedcopper=TRUE
13 further rules are at their usual default settings.

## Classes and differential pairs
component class Shunt: SH-J5 SH-J6 SH-J7
component class Header: J5 J6 J7
component class AssemblyNote: ZZ1 ZZ2 ZZ3 ZZ4 ZZ5 ZZ6
component class FiducialMark: FID1 FID2 FID3 FID4 FID5 FID6
component class Logo: Logo1
component class BSR155A_Hardware: !PCB FID1 FID2 FID3 FID4 FID5 FID6 Logo1 Logo2 Logo3 Logo4 SH-J5 SH-J6 SH-J7 ZZ1 ZZ2 ZZ3 ZZ4 ZZ5 ZZ6
component class BSR155A: C1 C2 C3 C4 C5 C6 C7 C8 C9 C10 C11 C12 C13 C14 C15 J1 J2 J3 J4 J5 J6 J7 NT1 R1 R2 R3 R4 R5 R6 R7 R8 R9 R10 R11 R12 R13 R14 R15 R16 R17 TP1 TP2 TP3 TP4 TP5 TP6 TP7 TP8 TP9 TP10 TP11 U1

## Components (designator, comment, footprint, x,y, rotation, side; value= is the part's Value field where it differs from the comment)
C1 "GRM31CC72A475KE11L" FP-GRM31CC72A475KE11L_1206-MFG 1679,1366 r180 top
C2 "GRM31CC72A475KE11L" FP-GRM31CC72A475KE11L_1206-MFG 1679,1082 r180 top
C3 "GRM31CC72A475KE11L" FP-GRM31CC72A475KE11L_1206-MFG 1678,1366 r180 bottom
C4 "GRM31CC72A475KE11L" FP-GRM31CC72A475KE11L_1206-MFG 1678,1082 r180 bottom
C5 "C3216X5R1E476M160AC" 1206_190L 1845,1330 r270 top
C6 "C3216X5R1E476M160AC" 1206_190L 1845,1118.85 r90 top
C7 "C3216X5R1E476M160AC" 1206_190L 1929,1329 r270 top
C8 "C3216X5R1E476M160AC" 1206_190L 1929,1119 r90 top
C9 "T520Y337M010ATE035" 7343-40 2267,1226 r270 top
C10 "EEEFT1H470AP" Panasonic_D 891.6,1086.6 r270 top
C11 "EMK105BJ105KVHF" 0402S 1465,1244 r180 top
C12 "GRM155R61E105KA12D" 0402S 1481,1294 r90 top
C13 "C0603C102J5RACTU" 0603 2146,667 r180 bottom
C14 "GRM188R71C472KA01D" 0603L 1429,1392 r90 bottom
FID1 "Fiducial" Fiducial10-20 2800,150 r0 top
FID2 "Fiducial" Fiducial10-20 450,2350 r0 top
FID3 "Fiducial" Fiducial10-20 2800,2350 r0 top
FID4 "Fiducial" Fiducial10-20 450,2350 r180 bottom
FID5 "Fiducial" Fiducial10-20 2800,2350 r180 bottom
FID6 "Fiducial" Fiducial10-20 2800,150 r180 bottom
J1 "OSTTA024163" On-Shore_OSTTA024163 308,1155 r270 top
J2 "310-43-102-41-001000" Mill-max_310-43-102-41-001000 1284,1226 r270 top
J3 "310-43-102-41-001000" Mill-max_310-43-102-41-001000 2075,1226 r270 top
J4 "OSTTA024163" On-Shore_OSTTA024163 2943,1160 r90 top
J5 "PEC03SAAN" CONN_PEC03SAAN 1692.07,666.47 r270 top
J6 "PEC05DAAN" CONN_PEC05DAAN 1087.13,1712.02 r0 top
J7 "PEC05DAAN" CONN_PEC05DAAN 1088,707 r180 top
Logo1 "Texas Instruments" TI_Stacked_Overlay_Small 2294,250 r0 top
Logo2 "CE Mark" CE_Mark_5mm 1923,326 r180 bottom
Logo3 "FCC disclaimer" FCC_disclaimer 1685,96 r180 bottom
Logo4 "WEEE logo" WEEE_Minimum 1486,356 r180 bottom
NT1 "Net-Tie" Net-Tie_10mil 1602,1226 r0 top net-tie
R1 "CRCW0603402KFKEA" 0603 1790,736 r90 bottom
R2 "CRCW0603133KFKEA" 0603 1789,596 r90 bottom
R3 "CRCW060349K9FKEA" 0603 1927,1765 r180 bottom
R4 "CRCW060320R0JNEA" 0603 2609,1602 r0 bottom
R5 "CRCW060310K0FKEA" 0603 1541,1271 r180 bottom
R6 "CRCW060315K0FKEA" 0603 1485,1366 r90 bottom
R7 "CRCW06038K06FKEA" 0603 1314.73,1568.52 r180 bottom
R8 "CRCW060316K9FKEA" 0603 1183.73,1568.52 r180 bottom
R9 "CRCW060324K9FKEA" 0603 1051.73,1568.52 r180 bottom
R10 "CRCW060345K3FKEA" 0603 920.13,1568.52 r180 bottom
R11 "CRCW060326K7FKEA" 0603 1288,879 r90 bottom
R12 "CRCW060317K4FKEA" 0603 1188,879 r90 bottom
R13 "CRCW060313K0FKEA" 0603 1088,879 r90 bottom
R14 "CRCW06038K66FKEA" 0603 988,879 r90 bottom
R15 "CRCW06036K34FKEA" 0603 888,879 r90 bottom
R16 "CRCW040210R0JNED" 0402S 1548,1368 r0 bottom
R17 "RMCF0603ZT0R00" 0603 1689,1154 r180 bottom
SH-J5 "2SN-BK-G" 2SN-BK-G 1691,722 r90 top
SH-J6 "2SN-BK-G" 2SN-BK-G 1087.13,1719.17 r90 top
SH-J7 "2SN-BK-G" 2SN-BK-G 1086.42,707.11 r90 top
TP1 "5010" Keystone5010 292,1600 r90 top
TP2 "5010" Keystone5010 2958,1600 r90 top
TP3 "5011" Keystone5011 292,750 r90 top
TP4 "5011" Keystone5011 2958,750 r90 top
TP5 "5012" Keystone5012 2104.73,1765 r180 top
TP6 "5012" Keystone5012 1765,1765 r180 top
TP7 "5012" Keystone5012 2285,667 r0 top
TP8 "TESTPOINT" TP_25MIL-SMT 1797,1225 r90 top
TP9 "5011" Keystone5011 2441,1765 r0 top
TP10 "5011" Keystone5011 2567,667 r0 top
TP11 "5012" Keystone5012 2003,667 r0 top
U1 "TPSM63603RDHR" RDH0030A-MFG 1655.45,1224.74 r90 top
ZZ1 "These assemblies are ESD sensitive, ESD precautions shall be observed." AssemblyNote -430,3004 r0 top
ZZ2 "These assemblies must be clean and free from flux and all contaminants. Use of no clean flux is not acceptable." AssemblyNote -430,3188 r0 top
ZZ3 "These assemblies must comply with workmanship standards IPC-A-610 Class 2, unless otherwise specified." AssemblyNote -430,3371 r0 top
ZZ4 "Place SH-J5 on J5 pins 2 and 3" AssemblyNote -425,3544 r0 top
ZZ5 "Place SH-J6 on J6 pins 5 and 6" AssemblyNote -434,3678 r0 top
ZZ6 "Place SH-J7 on J7 pins 5 and 6" AssemblyNote -434,3810 r0 top

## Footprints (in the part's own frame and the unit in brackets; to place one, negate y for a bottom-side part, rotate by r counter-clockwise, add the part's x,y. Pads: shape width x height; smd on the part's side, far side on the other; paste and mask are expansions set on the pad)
2SN-BK-G [mil] "Samtec STEP model"
  round 1 on Mech3: 0(0,0)
0402S [mil] "Based on C0402S footprint from PADS legacy"
  rect 15x24 smd: 1(-20,0) 2(20,0)
0603 [mm] "0603 from SM-752 data"
  rect 1x0.95 smd: 1(-0.8,0) 2(0.8,0)
  silkscreen extent -1.52,-0.69 1.52,0.69
0603L [mm] "0603 from SM-752 data"
  rect 0.8x0.85 smd: 1(-0.7,0) 2(0.7,0)
  silkscreen extent -0.07,-0.33 0.07,0.33
1206_190L [mm] "1206_190"
  rect 1.1x1.75 smd: 1(-1.35,0) 2(1.35,0)
  silkscreen extent -0.4,-0.77 0.4,0.77
7343-40 [mm] "Molded, 2-Leads, Body 7.3x4.3mm, Height 4mm"
  rect 2.4x2.9 smd: 1(-3.05,0) 2(3.05,0)
  silkscreen extent -3.8,-2.25 3.8,2.25
AssemblyNote [mil] "Assembly Note"
CE_Mark_5mm [mil] "Minimum text height for CE Mark"
CONN_PEC03SAAN [mm] "SULLINS"
  rect 1.5x1.5 hole 1.016: 1(-2.54,0)
  round 1.5 hole 1.016: 2(0,0) 3(2.54,0)
  silkscreen extent -4.72,-1.27 3.81,1.27
CONN_PEC05DAAN [mm] "SULLINS"
  rect 1.65x1.65 hole 1.016 mask+0: 1(-5.08,-1.27)
  round 1.65 hole 1.016 mask+0: 2(-5.08,1.27) 3(-2.54,-1.27) 4(-2.54,1.27) 5(0,-1.27) 6(0,1.27) 7(2.54,-1.27) 8(2.54,1.27) 9(5.08,-1.27) 10(5.08,1.27)
  silkscreen extent -7.45,-2.6 6.35,2.54
FCC_disclaimer [mil]
Fiducial10-20 [mm]
  round 1 smd mask+0: 1(0,0)
  Top Layer keep-out circle w1.178: c0,0 r0.5
FP-GRM31CC72A475KE11L_1206-MFG [mm]
  rrect9% 1.15x1.8 smd paste+0 mask+0: 1(-1.575,0) 2(1.575,0)
  silkscreen extent -0.63,-0.95 0.63,0.95
Keystone5010 [mil] "Keystone Multipurpose loops"
  round 87 hole 63: 1(0,0)
  silkscreen extent -70,-70 70,70
Keystone5011 [mil] "Keystone Multipurpose loops"
  round 87 hole 63: 1(0,0)
  silkscreen extent -70,-70 70,70
Keystone5012 [mil] "Keystone Multipurpose loops"
  round 87 hole 63: 1(0,0)
  silkscreen extent -70,-70 70,70
Mill-max_310-43-102-41-001000 [mm] "Mill-max"
  rect 1.35x1.35 hole 0.75: 1(-1.27,0)
  round 1.35 hole 0.75: 2(1.27,0)
  silkscreen extent -3.22,-1.3 2.6,1.3
Net-Tie_10mil [mil] "10mil net tie, no solder mask opening, no solder paste"
  rect 10x10 smd paste-5 mask+0: 1(-10,0) 2(10,0)
On-Shore_OSTTA024163 [mm] "TERM BLOCK 2x1, 5.08mm, TH"
  rect 1.8x1.8 hole 1.3: 1(-2.04,-0.5)
  round 1.8 hole 1.3 paste+0: 2(3.04,-0.5)
  silkscreen extent -7.18,-4.55 5.63,4.55
Panasonic_D [mm] "SMD, 2-Leads, Dia 6.3mm"
  rect 3.2x1.6 smd: 1(-2.5,0) 2(2.5,0)
  silkscreen extent -3.4,-3.4 3.4,3.4
RDH0030A-MFG [mm]
  rrect22% 0.93x1.05 smd paste-1000 mask+0: 1(-1.786,2.725) 8(-1.786,-2.725) 14(1.786,-2.725) 21(1.786,2.725)
  rrect57% 0.95x0.35 smd paste-1000 mask+0: 2(-1.775,1.775) 3(-1.775,0.975) 4(-1.775,0.325) 5(-1.775,-0.475) 6(-1.775,-1.125) 7(-1.775,-1.775) 15(1.775,-1.775) 16(1.775,-1.125) 17(1.775,-0.475) 18(1.775,0.325) 19(1.775,0.975) 20(1.775,1.775)
  rrect57% 0.35x0.8 smd paste-1000 mask+0: 9(-1,-2.85) 10(-0.5,-2.85) 11(0,-2.85) 12(0.5,-2.85) 13(1,-2.85) 22(1,2.85) 23(0.5,2.85) 24(0,2.85) 25(-0.5,2.85) 26(-1,2.85)
  rrect24% 1.35x0.84 smd paste-1000 mask+0: 27(0,1.925) 30(0,-1.925)
  rrect10% 1.6x1 smd paste-1000 mask+0: 28(0,0.6) 29(0,-0.6)
TI_Stacked_Overlay_Small [mil]
TP_25MIL-SMT [mil]
  round 20 smd mask+0: 1(0,0)
WEEE_Minimum [mil] "WEEElie bin"
  silkscreen extent 22,-71 54,74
